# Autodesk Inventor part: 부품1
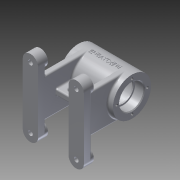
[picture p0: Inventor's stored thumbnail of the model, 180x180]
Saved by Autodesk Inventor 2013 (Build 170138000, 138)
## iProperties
Created: 2015-11
Part Number: 부품1
Material: 알루미늄 6061
Document SubType Name: Modeling
Designer: default
Density: 2.71 g/cm^3
Mass: 358.628 g
Surface Area: 460.303 cm^2
Volume: 132.335 cm^3
Author: default
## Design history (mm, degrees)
sketch "스케치1"
  geometry: C1 r 25 at (0, 0); 1 further point
  constraints: 1 centre point, 1 coincident
  dimensions: "d0" = 50 diameter of C1
extrude "돌출1" new body sketch "스케치1" distance "d2" = 70; taper "d3" = 0 deg
node "작업 평면1"
sketch "스케치2"
  geometry: L1 (0, 25)-(70, 25) reference; L2 (70, -25)-(70, 25) reference; L3 (0, 25)-(0, -25) reference; L4 (0, -25)-(70, -25) reference; L5 (15, -6.491)-(55, -6.491); L6 (55, -6.491)-(55, -45); L7 (55, -45)-(15, -45); L8 (15, -45)-(15, -6.491); 3 further points
  constraints: 8 end point, 2 midpoint, 2 parallel, 1 horizontal, 1 perpendicular, 1 vertical alignment
  dimensions: "d5" = 20 distance between parallel lines of L4 L7; "d6" = 40 distance of L5.start L5.end
extrude "돌출2" join sketch "스케치2" stored distance "d7" = 8; taper "d8" = 0 deg
sketch "스케치3"
  geometry: L1 (-21, 45)-(29, 45); L2 (29, 45)-(29, -23); L3 (29, -23)-(-21, -23); L4 (-21, -23)-(-21, 45); C1 r 25 at (4, 45) reference; A1 r 25 centre (4, 45) between (0, 20.322) and (8, 20.322) reference; 1 further point
  constraints: 8 end point, 2 midpoint, 2 parallel, 1 coincident, 1 horizontal, 1 perpendicular
  dimensions: "d9" = 68 distance from line of A1.centre L3; "d10" = 50 distance of L1.start L1.end
extrude "돌출3" join sketch "스케치3" distance "d11" = 8; taper "d12" = 0 deg
sketch "스케치4"
  geometry: L1 (0, 0)-(0, 50) reference; L2 (8, 50)-(8, 0) reference; L3 (0, 50)-(8, 50) reference; L4 (20, -15)-(20, 65); L5 (0, 65)-(0, -15); A1 r 10 centre (10, 65) between (20, 65) and (0, 65); A2 r 10 centre (10, -15) between (0, -15) and (20, -15); 4 further points
  constraints: 4 end point, 4 midpoint, 4 point on circle, 4 tangent, 2 centre point, 1 horizontal alignment, 1 parallel, 1 perpendicular
  dimensions: "d13" = 20 distance between parallel lines of L5 L4; "d15" = 80 distance of A2.centre A1.centre
extrude "돌출4" join sketch "스케치4" distance "d16" = 10; taper "d17" = 0 deg
sketch "스케치5"
  geometry: C1 r 10 at (10, 15); C2 r 10 at (10, -65); A1 r 10 centre (10, -65) between (0, -65) and (20, -65) reference; A2 r 10 centre (10, 15) between (20, 15) and (0, 15) reference; 1 further point
  constraints: 2 centre point, 2 coincident, 2 concentric
extrude "돌출5" join sketch "스케치5" distance "d18" = 3; taper "d19" = 0 deg
sketch "스케치6"
  geometry: C1 r 10 at (0, 0) reference; C2 r 10 at (0, 80) reference; 3 further points
  constraints: 2 coincident
hole "구멍1" sketch "스케치6" at (0, 80), (0, 0) diameter "d20" = 6; stored, may be unused: countersink angle "d24" = 90 deg, drill point angle "d26" = 118 deg; dims "d21" = 6, "d22" = 12, "d23" = 4, "d25" = 8
node "작업 평면2"
sketch "스케치7"
  geometry: L1 (-55, -24.678)-(-15, -24.678) reference; L2 (-15, -45)-(-15, -24.678) reference; L3 (-27, -31.5)-(-43, -31.5); L4 (-43, -38.5)-(-27, -38.5); L5 (5, -68)-(-15, -68) reference; A1 r 3.5 centre (-43, -35) between (-43, -31.5) and (-43, -38.5); A2 r 3.5 centre (-27, -35) between (-27, -38.5) and (-27, -31.5); 3 further points
  constraints: 4 end point, 4 point on circle, 4 tangent, 2 centre point, 2 midpoint, 1 parallel, 1 perpendicular, 1 vertical alignment
  dimensions: "d27" = 3.5 radius of A1; "d29" = 16 distance of A2.centre A1.centre; "d30" = 33 distance from line of L5 A2.centre
extrude "돌출6" cut sketch "스케치7" stored distance "d31" = 3; taper "d32" = 0 deg
node "작업 평면3"
sketch "스케치8"
  geometry: L1 (0, 25)-(-70, 25) reference; L2 (0, -25)-(0, 25) reference; C1 r 5 at (-35, 0); 3 further points
  constraints: 2 midpoint, 1 centre point, 1 horizontal alignment, 1 vertical alignment
  dimensions: "d34" = 10 diameter of C1
extrude "돌출7" join sketch "스케치8" distance "d36" = 28; taper "d37" = 0 deg
sketch "스케치9"
  geometry: L1 (0, 0)-(0, -21.987); L2 (0, 0)-(14, -24.249); L3 (19.196, -21.249)-(6.746, 0.316); L4 (14, -24.249)-(19.196, -21.249); L5 (6.746, 0.316)-(1.808, -3.131); C1 r 25 at (0, 0) reference; 1 further point
  constraints: 10 end point, 1 parallel, 1 perpendicular, 1 point on line, 1 vertical
  dimensions: "d38" = 30 deg angle of L2 L1; "d39" = 6 distance between parallel lines of L3 L2; "d41" = 28 distance from line of L4 point (0, 0)
revolve "회전1" sketch "스케치9" stored, may be unused: angle "d42" = 90 deg
sketch "스케치10"
  geometry: C1 r 25 at (0, 0) reference; C2 r 16 at (0, 0)
  constraints: 1 centre point, 1 coincident
  dimensions: "d43" = 32 diameter of C2
extrude "돌출8" cut sketch "스케치10" distance "d45" = 12; taper "d46" = 0 deg
sketch "스케치11"
  geometry: C1 r 16 at (0, 0) reference; C2 r 14 at (0, 0)
  constraints: 1 centre point, 1 coincident
  dimensions: "d47" = 28 diameter of C2
extrude "돌출9" cut sketch "스케치11" distance "d49" = 2; taper "d50" = 0 deg
sketch "스케치12"
  geometry: C1 r 25 at (0, 0) reference; C2 r 16 at (0, 0)
  constraints: 1 centre point, 1 coincident
  dimensions: "d51" = 32 diameter of C2
extrude "돌출10" cut sketch "스케치12" distance "d53" = 12; taper "d54" = 0 deg
sketch "스케치13"
  geometry: C1 r 16 at (0, 0) reference; C2 r 14 at (0, 0)
  constraints: 1 centre point, 1 coincident
  dimensions: "d55" = 28 diameter of C2
extrude "돌출11" cut sketch "스케치13" distance "d57" = 2; taper "d58" = 0 deg
sketch "스케치14"
  geometry: C1 r 14 at (0, 0) reference; C2 r 21 at (0, 0)
  constraints: 1 centre point, 1 coincident
  dimensions: "d59" = 42 diameter of C2
extrude "돌출12" cut sketch "스케치14" distance "d61" = 42; taper "d62" = 0 deg
sketch "스케치15"
  geometry: C1 r 5 at (0, 0) reference; 2 further points
  constraints: 1 coincident
hole "구멍2" sketch "스케치15" at (0, 0) diameter "d63" = 5.188; stored, may be unused: countersink angle "d67" = 90 deg, drill point angle "d69" = 118 deg; dims "d64" = 20, "d65" = 19.05, "d66" = 4.775, "d68" = 20
sketch "스케치16"
  geometry: C1 r 6 at (0, 0) reference; 2 further points
  constraints: 1 coincident
hole "구멍3" sketch "스케치16" at (0, 0) diameter "d70" = 5.188; stored, may be unused: countersink angle "d74" = 90 deg, drill point angle "d76" = 118 deg; dims "d71" = 20, "d72" = 19.05, "d73" = 4.775, "d75" = 20
sketch "스케치17" dims "d77" = 40
  geometry: L1 (0, 0)-(0, 20); C1 r 25 at (0, 0) reference; 1 further point
  constraints: 2 coincident, 2 end point, 1 vertical, 1 vertical alignment, 2 other
hole "구멍4" sketch "스케치17" at (0, 20) diameter "d79" = 3.242; stored, may be unused: countersink angle "d83" = 90 deg, drill point angle "d85" = 118 deg; dims "d80" = 8, "d81" = 19.05, "d82" = 4.775, "d84" = 10
node "작업 평면4"
sketch "스케치18"
  geometry: L1 (0, 25)-(0, -25) reference; L2 (0, 25)-(70, 25) reference; 2 further points
  constraints: 1 other
  dimensions: "d89" = 35 distance from line of point (35, 0) L1; "d90" = 25 distance from line of L2 point (35, 0)
feature "엠보싱1" sketch "스케치18" dims "d91" = 0.5, "d92" = 0
fillet "모깎기1" dims "d93" = 0.3
fillet "모깎기2" dims "d94" = 0.3
fillet "모깎기3" dims "d95" = 3
fillet "모깎기4" dims "d96" = 2
fillet "모깎기5" dims "d97" = 2
fillet "모깎기6" dims "d98" = 2
fillet "모깎기7" dims "d99" = 2
fillet "모깎기8" dims "d100" = 2
fillet "모깎기9" dims "d101" = 2
fillet "모깎기10" dims "d102" = 2
fillet "모깎기11" dims "d103" = 2
chamfer "모따기1" distance "d104" = 1; stored, may be unused: second distance "d105" = 2, angle "d106" = 45 deg
chamfer "모따기2" distance "d107" = 1; stored, may be unused: second distance "d108" = 2, angle "d109" = 45 deg
fillet "모깎기12" dims "d110" = 2
node "솔리드1"
mirror "대칭1"
pattern_circular "원형 패턴1" dims angle "d87" = 360 deg
mirror "대칭2"
node "투영된 루프1"
node "투영된 루프2"
node "투영된 루프3"
other parameters: "d4" = 0, "d33" = 0
